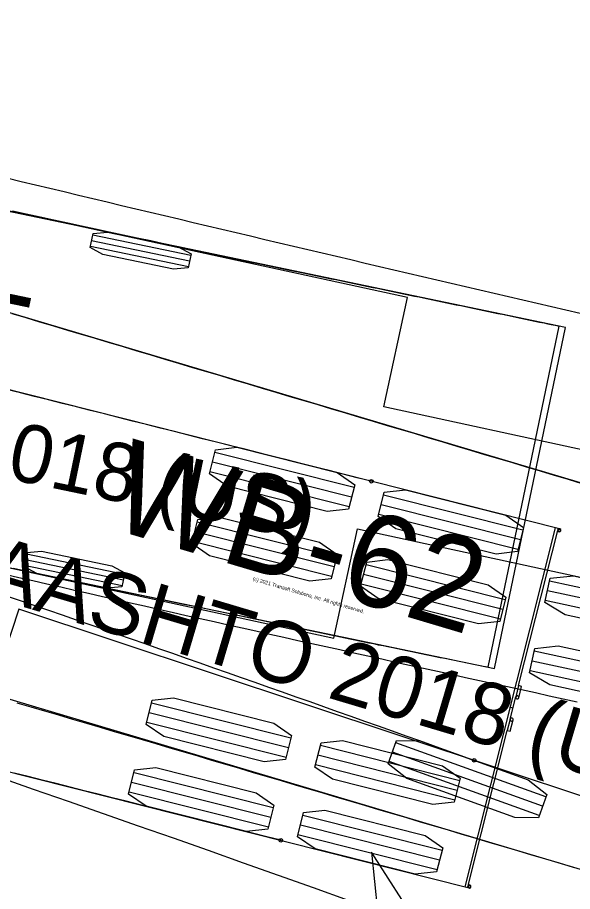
# Model space of a CAD drawing. Extents: x -14 to 1565148, y -25 to 642856.
# Drawn here: x 1565086.71 to 1565099.46, y 636499.5 to 636519.56 of the extents above; entities that cross this region are included whole.
import ezdxf

# ---------------------------------------------------------------- set-up
doc = ezdxf.new("R2010")
doc.units = 0
for name, color, linetype in [('GE_P_Alignment_100_Stations', 7, 'Continuous'), ('PM_P_Edge_Line', 7, 'Continuous'), ('TR_Turning_Path27', 7, 'Continuous'), ('TR_Turning_Path29', 7, 'Continuous')]:
    doc.layers.add(name, color=color, linetype=linetype)

msp = doc.modelspace()

# ---------------------------------------------------------------- linework, layer by layer
at = {"layer": 'GE_P_Alignment_100_Stations'}
for p, q in [((1565117.99, 636503.414), (1565071.987, 636517.115)), ((1565095.666, 636513.135), (1565081.006, 636516.311)), ((1565095.123, 636510.627), (1565095.666, 636513.135)), ((1565105.483, 636508.383), (1565095.123, 636510.627)), ((1565069.561, 636508.968), (1565115.564, 636495.268)), ((1565079.313, 636508.493), (1565093.972, 636505.317)), ((1565093.972, 636505.317), (1565094.516, 636507.825)), ((1565094.516, 636507.825), (1565104.876, 636505.581)), ((1565098.931, 636506.634), (1565102.514, 636505.858)), ((1565098.882, 636506.41), (1565102.466, 636505.634)), ((1565098.833, 636506.186), (1565102.417, 636505.41)), ((1565098.581, 636505.022), (1565102.165, 636504.245)), ((1565098.533, 636504.798), (1565102.116, 636504.021)), ((1565098.484, 636504.574), (1565102.068, 636503.797))]:
    msp.add_line(p, q, dxfattribs=at)
for points in [[(1565086.459, 636515.88), (1565086.789, 636515.802), (1565087.118, 636515.723), (1565087.447, 636515.644), (1565087.777, 636515.566), (1565088.106, 636515.487), (1565088.435, 636515.409), (1565088.765, 636515.33), (1565089.094, 636515.252), (1565089.423, 636515.174), (1565089.753, 636515.095), (1565090.082, 636515.017), (1565090.412, 636514.939), (1565090.741, 636514.861), (1565091.07, 636514.783), (1565091.4, 636514.705), (1565091.729, 636514.627), (1565092.059, 636514.549), (1565092.388, 636514.471), (1565092.717, 636514.393), (1565093.047, 636514.315), (1565093.376, 636514.238), (1565093.706, 636514.16), (1565094.035, 636514.082), (1565094.365, 636514.005), (1565094.694, 636513.928), (1565095.024, 636513.85), (1565095.353, 636513.773), (1565095.683, 636513.696), (1565096.012, 636513.619), (1565096.342, 636513.541), (1565096.672, 636513.464), (1565097.001, 636513.388), (1565097.331, 636513.311), (1565097.66, 636513.234), (1565097.99, 636513.157), (1565098.319, 636513.08), (1565098.649, 636513.004), (1565098.979, 636512.927), (1565099.308, 636512.851), (1565099.638, 636512.774)], [(1565086.574, 636512.77), (1565086.894, 636512.675), (1565087.213, 636512.58), (1565087.533, 636512.485), (1565087.852, 636512.39), (1565088.172, 636512.294), (1565088.492, 636512.199), (1565088.811, 636512.104), (1565089.131, 636512.009), (1565089.45, 636511.914), (1565089.77, 636511.819), (1565090.089, 636511.723), (1565090.409, 636511.628), (1565090.728, 636511.533), (1565091.048, 636511.438), (1565091.367, 636511.343), (1565091.687, 636511.248), (1565092.006, 636511.153), (1565092.326, 636511.057), (1565092.645, 636510.962), (1565092.965, 636510.867), (1565093.284, 636510.772), (1565093.604, 636510.677), (1565093.923, 636510.582), (1565094.243, 636510.486), (1565094.562, 636510.391), (1565094.882, 636510.296), (1565095.201, 636510.201), (1565095.521, 636510.106), (1565095.84, 636510.011), (1565096.16, 636509.916), (1565096.479, 636509.82), (1565096.799, 636509.725), (1565097.118, 636509.63), (1565097.438, 636509.535), (1565097.757, 636509.44), (1565098.077, 636509.345), (1565098.396, 636509.249), (1565098.716, 636509.154), (1565099.035, 636509.059), (1565099.355, 636508.964), (1565099.674, 636508.869)], [(1565099.568, 636503.849), (1565099.247, 636503.918), (1565098.926, 636503.988), (1565098.605, 636504.058), (1565098.283, 636504.128), (1565097.962, 636504.198), (1565097.641, 636504.268), (1565097.32, 636504.338), (1565096.999, 636504.408), (1565096.678, 636504.479), (1565096.357, 636504.549), (1565096.036, 636504.62), (1565095.715, 636504.69), (1565095.394, 636504.761), (1565095.074, 636504.832), (1565094.753, 636504.903), (1565094.432, 636504.974), (1565094.111, 636505.045), (1565093.79, 636505.116), (1565093.469, 636505.187), (1565093.149, 636505.258), (1565092.828, 636505.33), (1565092.507, 636505.401), (1565092.186, 636505.473), (1565091.866, 636505.545), (1565091.545, 636505.616), (1565091.224, 636505.688), (1565090.904, 636505.76), (1565090.583, 636505.832), (1565090.262, 636505.904), (1565089.942, 636505.977), (1565089.621, 636506.049), (1565089.301, 636506.121), (1565088.98, 636506.194), (1565088.66, 636506.266), (1565088.339, 636506.339), (1565088.019, 636506.412), (1565087.698, 636506.485), (1565087.378, 636506.557), (1565087.057, 636506.63), (1565086.737, 636506.704), (1565086.417, 636506.777)], [(1565099.483, 636500.052), (1565099.163, 636500.147), (1565098.844, 636500.242), (1565098.524, 636500.337), (1565098.205, 636500.431), (1565097.885, 636500.526), (1565097.566, 636500.621), (1565097.246, 636500.716), (1565096.926, 636500.81), (1565096.607, 636500.905), (1565096.287, 636500.999), (1565095.968, 636501.094), (1565095.648, 636501.189), (1565095.328, 636501.283), (1565095.009, 636501.378), (1565094.689, 636501.472), (1565094.37, 636501.567), (1565094.05, 636501.661), (1565093.73, 636501.756), (1565093.411, 636501.85), (1565093.091, 636501.945), (1565092.772, 636502.039), (1565092.452, 636502.133), (1565092.132, 636502.228), (1565091.813, 636502.322), (1565091.493, 636502.416), (1565091.173, 636502.51), (1565090.854, 636502.605), (1565090.534, 636502.699), (1565090.214, 636502.793), (1565089.895, 636502.887), (1565089.575, 636502.981), (1565089.255, 636503.075), (1565088.936, 636503.169), (1565088.616, 636503.263), (1565088.296, 636503.357), (1565087.977, 636503.451), (1565087.657, 636503.545), (1565087.337, 636503.639), (1565087.017, 636503.733), (1565086.698, 636503.827)]]:
    msp.add_lwpolyline(points, dxfattribs=at)
for points in [[(1565098.821, 636506.131), (1565098.943, 636506.69), (1565099.481, 636506.75), (1565102.061, 636506.191), (1565102.526, 636505.914), (1565102.405, 636505.354), (1565101.867, 636505.295), (1565099.287, 636505.854)], [(1565098.472, 636504.518), (1565098.593, 636505.077), (1565099.131, 636505.137), (1565101.712, 636504.578), (1565102.177, 636504.301), (1565102.056, 636503.742), (1565101.517, 636503.682), (1565098.937, 636504.241)]]:
    msp.add_lwpolyline(points, close=True, dxfattribs=at)
at = {"layer": 'PM_P_Edge_Line'}
for p, q in [((1565099.296, 636512.449), (1565072.86, 636517.941)), ((1565088.408, 636514.445), (1565090.66, 636513.977)), ((1565088.434, 636514.573), (1565090.686, 636514.105)), ((1565088.381, 636514.318), (1565090.633, 636513.85)), ((1565097.669, 636504.616), (1565099.296, 636512.449)), ((1565071.233, 636510.108), (1565097.669, 636504.616)), ((1565086.913, 636507.25), (1565089.165, 636506.782)), ((1565086.86, 636506.995), (1565089.112, 636506.527)), ((1565086.886, 636507.122), (1565089.138, 636506.654))]:
    msp.add_line(p, q, dxfattribs=at)
for points in [[(1565086.59, 636515.125), (1565086.908, 636515.056), (1565087.226, 636514.988), (1565087.544, 636514.919), (1565087.862, 636514.851), (1565088.18, 636514.782), (1565088.498, 636514.714), (1565088.816, 636514.646), (1565089.134, 636514.577), (1565089.452, 636514.509), (1565089.77, 636514.441), (1565090.088, 636514.372), (1565090.406, 636514.304), (1565090.724, 636514.236), (1565091.043, 636514.168), (1565091.361, 636514.1), (1565091.679, 636514.032), (1565091.998, 636513.965), (1565092.316, 636513.899), (1565092.635, 636513.833), (1565092.954, 636513.767), (1565093.273, 636513.7), (1565093.592, 636513.634), (1565093.698, 636513.612), (1565093.805, 636513.59), (1565093.911, 636513.568), (1565094.017, 636513.546), (1565094.124, 636513.524), (1565094.23, 636513.501), (1565094.336, 636513.479), (1565094.443, 636513.457), (1565094.549, 636513.435), (1565094.655, 636513.413), (1565094.762, 636513.391), (1565094.868, 636513.369), (1565094.974, 636513.347), (1565095.081, 636513.325), (1565095.187, 636513.303), (1565095.293, 636513.28), (1565095.4, 636513.258), (1565095.506, 636513.236), (1565095.612, 636513.214), (1565095.719, 636513.192), (1565095.825, 636513.17), (1565095.932, 636513.148), (1565096.038, 636513.126), (1565096.144, 636513.104), (1565096.251, 636513.082), (1565096.357, 636513.06), (1565096.463, 636513.037), (1565096.57, 636513.015), (1565096.676, 636512.993), (1565096.783, 636512.971), (1565096.889, 636512.949), (1565096.996, 636512.927), (1565097.102, 636512.905), (1565097.209, 636512.883), (1565097.315, 636512.86), (1565097.422, 636512.838), (1565097.528, 636512.816), (1565097.635, 636512.794), (1565097.741, 636512.772), (1565097.848, 636512.75), (1565097.954, 636512.728), (1565098.061, 636512.706), (1565098.167, 636512.683), (1565098.274, 636512.661), (1565098.381, 636512.639), (1565098.487, 636512.617), (1565098.594, 636512.595), (1565098.7, 636512.573), (1565098.807, 636512.551), (1565098.889, 636512.533), (1565098.931, 636512.525), (1565098.972, 636512.516), (1565099.015, 636512.507), (1565099.057, 636512.499), (1565099.1, 636512.49), (1565099.144, 636512.481), (1565097.515, 636504.647)], [(1565097.515, 636504.647), (1565097.405, 636504.669), (1565097.296, 636504.691), (1565097.186, 636504.713), (1565097.077, 636504.735), (1565096.967, 636504.757), (1565096.858, 636504.78), (1565096.748, 636504.802), (1565096.639, 636504.824), (1565096.529, 636504.846), (1565096.42, 636504.868), (1565096.311, 636504.891), (1565096.201, 636504.913), (1565096.092, 636504.935), (1565095.983, 636504.957), (1565095.873, 636504.98), (1565095.764, 636505.002), (1565095.655, 636505.025), (1565095.546, 636505.047), (1565095.436, 636505.069), (1565095.327, 636505.092), (1565095.218, 636505.114), (1565095.109, 636505.137), (1565095, 636505.159), (1565094.89, 636505.182), (1565094.781, 636505.204), (1565094.672, 636505.227), (1565094.563, 636505.25), (1565094.454, 636505.272), (1565094.345, 636505.295), (1565094.236, 636505.318), (1565094.127, 636505.34), (1565094.017, 636505.363), (1565093.908, 636505.386), (1565093.799, 636505.408), (1565093.69, 636505.431), (1565093.581, 636505.454), (1565093.472, 636505.477), (1565093.363, 636505.5), (1565093.254, 636505.522), (1565093.145, 636505.545), (1565093.036, 636505.568), (1565092.927, 636505.591), (1565092.818, 636505.614), (1565092.709, 636505.637), (1565092.599, 636505.659), (1565092.49, 636505.682), (1565092.381, 636505.705), (1565092.272, 636505.728), (1565092.163, 636505.75), (1565091.836, 636505.819), (1565091.509, 636505.887), (1565091.182, 636505.956), (1565090.855, 636506.024), (1565090.528, 636506.092), (1565090.201, 636506.161), (1565089.874, 636506.229), (1565089.548, 636506.297), (1565089.221, 636506.365), (1565088.894, 636506.434), (1565088.567, 636506.502), (1565088.241, 636506.57), (1565087.914, 636506.639), (1565087.588, 636506.707), (1565087.261, 636506.775), (1565086.935, 636506.844), (1565086.608, 636506.912)]]:
    msp.add_lwpolyline(points, dxfattribs=at)
for points in [[(1565088.375, 636514.286), (1565088.441, 636514.604), (1565088.776, 636514.635), (1565090.397, 636514.298), (1565090.693, 636514.136), (1565090.626, 636513.818), (1565090.291, 636513.788), (1565088.67, 636514.125)], [(1565086.853, 636506.963), (1565086.919, 636507.281), (1565087.255, 636507.312), (1565088.876, 636506.975), (1565089.171, 636506.814), (1565089.105, 636506.495), (1565088.77, 636506.465), (1565087.149, 636506.802)]]:
    msp.add_lwpolyline(points, close=True, dxfattribs=at)
at = {"layer": 'TR_Turning_Path27'}
for p, q in [((1565086.739, 636505.984), (1565085.931, 636503.548)), ((1565100.976, 636501.258), (1565086.739, 636505.984)), ((1565098.848, 636501.675), (1565095.398, 636502.916)), ((1565098.771, 636501.459), (1565095.32, 636502.7)), ((1565098.693, 636501.243), (1565095.243, 636502.484))]:
    msp.add_line(p, q, dxfattribs=at)
for points in [[(1565086.471, 636506.283), (1565086.788, 636506.175), (1565087.104, 636506.066), (1565087.42, 636505.957), (1565087.736, 636505.848), (1565088.052, 636505.738), (1565088.369, 636505.629), (1565088.685, 636505.519), (1565089.001, 636505.41), (1565089.317, 636505.3), (1565089.633, 636505.19), (1565089.948, 636505.08), (1565090.264, 636504.969), (1565090.58, 636504.859), (1565090.896, 636504.749), (1565091.211, 636504.638), (1565091.527, 636504.527), (1565091.843, 636504.416), (1565092.158, 636504.305), (1565092.474, 636504.194), (1565092.789, 636504.083), (1565093.105, 636503.971), (1565093.42, 636503.86), (1565093.735, 636503.748), (1565094.051, 636503.636), (1565094.366, 636503.524), (1565094.681, 636503.412), (1565094.996, 636503.3), (1565095.311, 636503.188), (1565095.626, 636503.075), (1565095.941, 636502.963), (1565096.256, 636502.85), (1565096.571, 636502.737), (1565096.886, 636502.624), (1565097.201, 636502.511)], [(1565095.919, 636498.722), (1565094.838, 636500.404), (1565094.978, 636499.06), (1565094.014, 636498.113), (1565095.919, 636498.722)]]:
    msp.add_lwpolyline(points, dxfattribs=at)
for points in [[(1565098.867, 636501.728), (1565098.674, 636501.19), (1565098.133, 636501.201), (1565095.648, 636502.095), (1565095.224, 636502.431), (1565095.417, 636502.969), (1565095.959, 636502.958), (1565098.443, 636502.064)], [(1565095.919, 636498.722), (1565094.838, 636500.404), (1565094.978, 636499.06), (1565094.014, 636498.113)]]:
    msp.add_lwpolyline(points, close=True, dxfattribs=at)
msp.add_circle((1565097.201, 636502.511), 0.0417, dxfattribs=at)
msp.add_arc((1564828.253, 635754.783), 790.626, 70.211484, 74.167159, dxfattribs=at)
at = {"layer": 'TR_Turning_Path29'}
for p, q in [((1565099.13, 636507.833), (1565052.659, 636519.564)), ((1565050.578, 636511.323), (1565097.05, 636499.591)), ((1565091.24, 636509.588), (1565094.44, 636508.78)), ((1565091.184, 636509.366), (1565094.384, 636508.558)), ((1565091.128, 636509.144), (1565094.328, 636508.336)), ((1565095.119, 636508.609), (1565098.318, 636507.801)), ((1565095.063, 636508.387), (1565098.262, 636507.579)), ((1565090.837, 636507.988), (1565094.036, 636507.181)), ((1565095.007, 636508.165), (1565098.206, 636507.357)), ((1565099.062, 636507.85), (1565096.981, 636499.609)), ((1565098.229, 636504.262), (1565099.119, 636507.787)), ((1565099.119, 636507.787), (1565099.119, 636507.788)), ((1565099.125, 636507.811), (1565099.13, 636507.833)), ((1565090.781, 636507.766), (1565093.98, 636506.958)), ((1565090.724, 636507.544), (1565093.924, 636506.736)), ((1565094.715, 636507.009), (1565097.915, 636506.201)), ((1565094.659, 636506.787), (1565097.858, 636505.979)), ((1565094.603, 636506.565), (1565097.802, 636505.757)), ((1565098.22, 636504.227), (1565098.155, 636503.97)), ((1565098.22, 636504.227), (1565098.229, 636504.262)), ((1565098.288, 636504.21), (1565098.22, 636504.227)), ((1565098.223, 636503.95), (1565098.288, 636504.208)), ((1565098.288, 636504.208), (1565098.288, 636504.21)), ((1565098.026, 636503.46), (1565098.155, 636503.968)), ((1565089.788, 636503.835), (1565092.988, 636503.027)), ((1565089.732, 636503.613), (1565092.932, 636502.805)), ((1565098.09, 636503.712), (1565098.022, 636503.729)), ((1565089.676, 636503.391), (1565092.876, 636502.583)), ((1565098.025, 636503.454), (1565097.96, 636503.197)), ((1565098.029, 636503.181), (1565098.094, 636503.439)), ((1565097.061, 636499.637), (1565097.951, 636503.162)), ((1565097.951, 636503.162), (1565097.96, 636503.197)), ((1565097.96, 636503.197), (1565098.028, 636503.18)), ((1565098.028, 636503.18), (1565098.029, 636503.181)), ((1565093.667, 636502.856), (1565096.866, 636502.048)), ((1565093.61, 636502.634), (1565096.81, 636501.826)), ((1565093.554, 636502.412), (1565096.754, 636501.604)), ((1565089.384, 636502.235), (1565092.584, 636501.428)), ((1565089.328, 636502.013), (1565092.528, 636501.205)), ((1565089.272, 636501.791), (1565092.472, 636500.983)), ((1565093.263, 636501.256), (1565096.462, 636500.449)), ((1565093.207, 636501.034), (1565096.406, 636500.226)), ((1565093.15, 636500.812), (1565096.35, 636500.004)), ((1565097.05, 636499.591), (1565097.055, 636499.613)), ((1565097.061, 636499.636), (1565097.061, 636499.637))]:
    msp.add_line(p, q, dxfattribs=at)
for points in [[(1565094.836, 636508.917), (1565094.512, 636508.998), (1565094.189, 636509.08), (1565093.866, 636509.162), (1565093.543, 636509.243), (1565093.22, 636509.325), (1565092.897, 636509.406), (1565092.574, 636509.488), (1565092.251, 636509.569), (1565091.928, 636509.651), (1565091.605, 636509.732), (1565091.282, 636509.814), (1565090.959, 636509.895), (1565090.637, 636509.976), (1565090.314, 636510.058), (1565089.992, 636510.139), (1565089.67, 636510.22), (1565089.348, 636510.301), (1565089.026, 636510.382), (1565088.704, 636510.463), (1565088.383, 636510.544), (1565088.061, 636510.625), (1565087.74, 636510.705), (1565087.419, 636510.786), (1565087.098, 636510.866), (1565086.778, 636510.946), (1565086.457, 636511.026)], [(1565092.755, 636500.675), (1565092.432, 636500.757), (1565092.109, 636500.839), (1565091.785, 636500.92), (1565091.462, 636501.002), (1565091.139, 636501.083), (1565090.816, 636501.165), (1565090.493, 636501.246), (1565090.171, 636501.328), (1565089.848, 636501.409), (1565089.525, 636501.491), (1565089.203, 636501.572), (1565088.881, 636501.653), (1565088.559, 636501.734), (1565088.237, 636501.815), (1565087.915, 636501.897), (1565087.594, 636501.977), (1565087.273, 636502.058), (1565086.952, 636502.139), (1565086.631, 636502.22)]]:
    msp.add_lwpolyline(points, dxfattribs=at)
for points in [[(1565091.114, 636509.089), (1565091.254, 636509.643), (1565091.745, 636509.697), (1565094.048, 636509.116), (1565094.454, 636508.835), (1565094.314, 636508.281), (1565093.824, 636508.227), (1565091.52, 636508.808)], [(1565094.993, 636508.11), (1565095.133, 636508.664), (1565095.623, 636508.718), (1565097.927, 636508.137), (1565098.332, 636507.856), (1565098.192, 636507.302), (1565097.702, 636507.248), (1565095.398, 636507.829)], [(1565090.711, 636507.489), (1565090.851, 636508.043), (1565091.341, 636508.097), (1565093.644, 636507.516), (1565094.05, 636507.236), (1565093.91, 636506.681), (1565093.42, 636506.627), (1565091.116, 636507.209)], [(1565094.589, 636506.51), (1565094.729, 636507.064), (1565095.219, 636507.118), (1565097.523, 636506.537), (1565097.928, 636506.257), (1565097.788, 636505.702), (1565097.298, 636505.648), (1565094.995, 636506.23)], [(1565089.662, 636503.336), (1565089.802, 636503.89), (1565090.292, 636503.944), (1565092.596, 636503.363), (1565093.002, 636503.083), (1565092.862, 636502.528), (1565092.372, 636502.474), (1565090.068, 636503.056)], [(1565093.54, 636502.357), (1565093.68, 636502.911), (1565094.171, 636502.965), (1565096.474, 636502.384), (1565096.88, 636502.104), (1565096.74, 636501.549), (1565096.25, 636501.495), (1565093.946, 636502.076)], [(1565089.258, 636501.736), (1565089.398, 636502.291), (1565089.888, 636502.345), (1565092.192, 636501.763), (1565092.598, 636501.483), (1565092.458, 636500.928), (1565091.968, 636500.874), (1565089.664, 636501.456)], [(1565093.137, 636500.757), (1565093.277, 636501.311), (1565093.767, 636501.365), (1565096.07, 636500.784), (1565096.476, 636500.504), (1565096.336, 636499.949), (1565095.846, 636499.895), (1565093.542, 636500.477)]]:
    msp.add_lwpolyline(points, close=True, dxfattribs=at)
for centre, radius in [((1565094.836, 636508.917), 0.0417), ((1565099.155, 636507.791), 0.0266), ((1565092.755, 636500.675), 0.0417), ((1565097.091, 636499.616), 0.0266)]:
    msp.add_circle(centre, radius, dxfattribs=at)
for centre, radius, start, end in [((1565099.155, 636507.791), 0.0363, 185.5923, 146.755), ((1565098.189, 636503.959), 0.0352, 165.2297, 345.8162), ((1565098.189, 636503.959), 0.0354, 350.1233, 162.3088), ((1565098.06, 636503.448), 0.0352, 165.6193, 348.2587), ((1565098.06, 636503.448), 0.0352, 345.8473, 166.4338), ((1565097.091, 636499.616), 0.0363, 184.9086, 146.0712)]:
    msp.add_arc(centre, radius, start, end, dxfattribs=at)

# ---------------------------------------------------------------- texts
at = {"layer": 'GE_P_Alignment_100_Stations'}
for s, height, p in [('WB-62', 2.125, (1565088.732, 636507.87)), ('AASHTO 2018 (US)', 1.41667, (1565085.82, 636506.336)), ('(c) 2021 Transoft Solutions, Inc. All rights reserved.', 0.085, (1565092.103, 636506.645))]:
    msp.add_text(s, height=height, rotation=343.4153, dxfattribs=at).set_placement(p)
at = {"layer": 'PM_P_Edge_Line'}
for s, height, p in [('P-T', 2, (1565082.453, 636512.026)), ('AASHTO 2018 (US)', 1.33333, (1565077.793, 636510.781))]:
    msp.add_text(s, height=height, rotation=348.2636, dxfattribs=at).set_placement(p)

doc.saveas('drawing.dxf')
